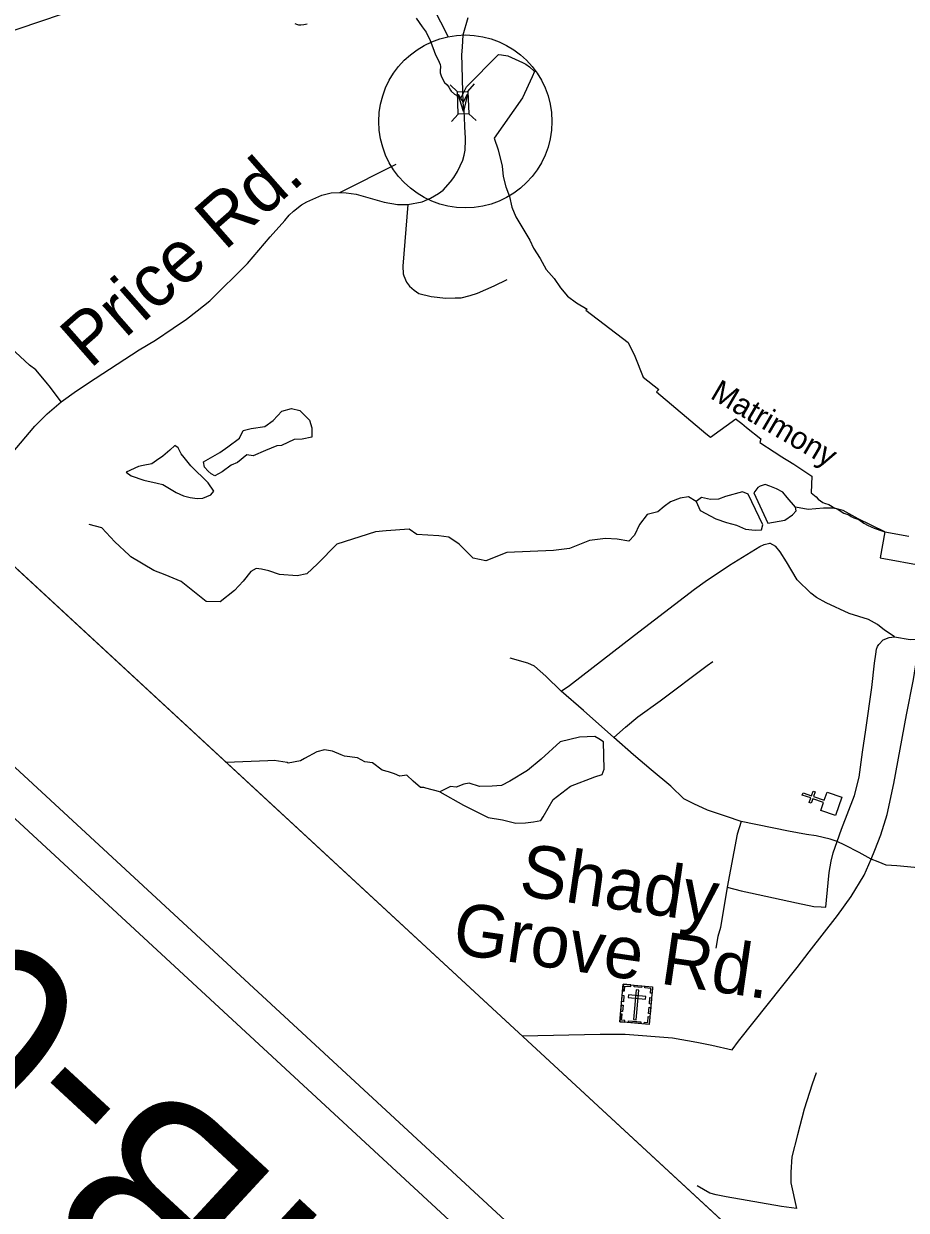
# Model space of a CAD drawing. Extents: x 1766669 to 1770980, y 998119 to 1002502.
# Drawn here: x 1767070.6 to 1767327.3, y 999494 to 999839.2 of the extents above; entities that cross this region are included whole.
import ezdxf

# ---------------------------------------------------------------- set-up
doc = ezdxf.new("R2010")
doc.units = 0
for name, color, linetype in [('Default', 7, 'Continuous'), ('Default Symbol CELL', 7, 'Continuous'), ('Exist DTM Breakline', 7, 'Continuous'), ('Exist DTM Drainline', 7, 'Continuous'), ('Exist DTM Regular Point CELL', 7, 'Continuous'), ('Exist Other Culture Dam', 7, 'Continuous'), ('Exist Property Text', 7, 'Continuous'), ('Exist Roads EOP', 7, 'Continuous'), ('Exist Roads EOP Other', 7, 'Continuous'), ('Exist Structure Minor Paved Ditch or Gutter', 7, 'Continuous'), ('Exist Structure Minor Pipes RCP 24 Inch', 7, 'Continuous'), ('Exist Survey Setup Group', 7, 'Continuous'), ('Exist Utilities Sanitary Sewer UG Line', 7, 'Continuous')]:
    doc.layers.add(name, color=color, linetype=linetype)

msp = doc.modelspace()

# ---------------------------------------------------------------- linework, layer by layer
at = {"layer": 'Default'}
msp.add_lwpolyline([(1766911.45, 999825.82), (1767342.39, 1000292.03), (1767769.56, 999897.17), (1767338.62, 999430.96)], close=True, dxfattribs=at)
at = {"layer": 'Default Symbol CELL'}
for p, q in [((1768196.36, 998579.87), (1766849, 999825.3)), ((1767395.61, 999378.28), (1766911.45, 999825.82)), ((1768487.42, 998295.86), (1766841.54, 999817.23))]:
    msp.add_line(p, q, dxfattribs=at)
msp.add_lwpolyline([(1767251.23, 999959.27), (1767173.81, 999875.14), (1767194.02, 999835.43)], dxfattribs=at)
at = {"layer": 'Exist DTM Breakline'}
msp.add_line((1767162.57, 999790.09), (1767178.91, 999798.33), dxfattribs=at)
for points in [[(1767198.42, 999816.26), (1767198.19, 999823.02), (1767198.13, 999827.11), (1767198.01, 999830.13), (1767198.18, 999832.42), (1767198.42, 999835.93), (1767199.89, 999841.01)], [(1767182.29, 999786.59), (1767186.45, 999787.39), (1767188.87, 999788.48), (1767191.25, 999789.82), (1767192.56, 999790.83), (1767194.68, 999793.2), (1767195.68, 999794.51), (1767196.72, 999796.25), (1767198.27, 999799.52), (1767198.71, 999801), (1767198.97, 999802.4), (1767199.09, 999805.38), (1767199.11, 999805.93), (1767198.93, 999809.18), (1767198.82, 999812.13), (1767198.69, 999813.48), (1767198.42, 999816.26)], [(1767135.72, 999769.45), (1767142.25, 999777.24), (1767146.52, 999781.96), (1767147.79, 999783.52), (1767149.02, 999784.66), (1767151.39, 999786.48), (1767152.91, 999787.42), (1767157.27, 999789.37), (1767160.02, 999789.97), (1767162.57, 999790.09)], [(1767162.57, 999790.09), (1767164.4, 999790.03), (1767167.31, 999789.62), (1767175.39, 999787.26), (1767179.28, 999786.58), (1767182.29, 999786.59)], [(1767182.29, 999786.59), (1767180.86, 999768.68), (1767180.99, 999766.43), (1767181.18, 999765.84), (1767181.94, 999764.03), (1767182.75, 999762.83), (1767184.15, 999761.66), (1767185.48, 999760.74), (1767189.1, 999759.81), (1767193.37, 999759.33), (1767196.1, 999759.47), (1767197.85, 999759.46), (1767200.41, 999760.14), (1767202.58, 999760.81), (1767207.45, 999762.96), (1767211.17, 999764.78)], [(1767081.5, 999729.23), (1767078.42, 999733.41), (1767077.12, 999734.95), (1767074.1, 999738.51), (1767072.32, 999739.83), (1767062.55, 999748.8), (1767058.99, 999752.71), (1767057.13, 999754.84), (1767056.29, 999756.3), (1767056.33, 999757.04), (1767056.65, 999758.12), (1767058.82, 999761.77), (1767059.06, 999762.9), (1767059.05, 999763.97), (1767058.97, 999764.77), (1767057.44, 999767.04), (1767055.19, 999770.52), (1767050.27, 999776.85), (1767048.82, 999778.68), (1767047.32, 999780.81)], [(1767081.5, 999729.23), (1767085.92, 999732.4), (1767091.36, 999735.95), (1767104.2, 999744.3), (1767108.93, 999747.18), (1767114.06, 999750.61), (1767117.9, 999753.21), (1767121.07, 999755.65), (1767124.73, 999758.54), (1767135.72, 999769.45)], [(1767052.3, 999695.62), (1767067.05, 999714.05), (1767073.82, 999722.16), (1767077.44, 999725.69), (1767081.5, 999729.23)], [(1767226.89, 999644.97), (1767229.34, 999646.69), (1767248.2, 999661.3), (1767265.7, 999674.72), (1767268.75, 999676.94), (1767275.85, 999681.71), (1767284.63, 999687.14), (1767285.9, 999687.73), (1767287.56, 999688.12)], [(1767323.81, 999660.83), (1767322.91, 999661.46), (1767320.91, 999662.73), (1767318.86, 999664.42), (1767316.25, 999665.91), (1767310.68, 999667.58), (1767303.93, 999670.73), (1767301.14, 999672.22), (1767299.46, 999673.51), (1767295.58, 999677.42), (1767292.43, 999682.6), (1767290.56, 999685.51), (1767289.35, 999687.13), (1767287.56, 999688.12)], [(1767307.12, 999601.28), (1767308.43, 999604.89), (1767312.17, 999614.61), (1767313.54, 999619.98), (1767314.56, 999627.3), (1767315.5, 999633.74), (1767317.22, 999646.05), (1767317.99, 999653.16), (1767318.4, 999655.82), (1767318.57, 999657.28), (1767318.9, 999657.99), (1767319.33, 999658.58), (1767320.58, 999659.91), (1767322.28, 999660.6), (1767323.81, 999660.83)], [(1767317.09, 999596.14), (1767318.12, 999598.72), (1767319.91, 999603.19), (1767321.74, 999609.09), (1767323.61, 999618.13), (1767327.36, 999638.16), (1767329.35, 999648.37), (1767330.48, 999655.24), (1767331.7, 999660.2)], [(1767323.81, 999660.83), (1767328.39, 999660.05), (1767331.7, 999660.2)], [(1767226.89, 999644.97), (1767222.41, 999649.4), (1767219.19, 999652.26), (1767217.22, 999653.2), (1767212.02, 999654.58)], [(1767242.21, 999631.49), (1767245.62, 999634.53), (1767249.22, 999637.51), (1767255.7, 999642.18), (1767269.35, 999652.51), (1767270.98, 999653.65)], [(1767242.21, 999631.49), (1767233.35, 999639.35), (1767226.89, 999644.97)], [(1767279.2, 999607.1), (1767274.97, 999608.52), (1767269.44, 999610.43), (1767265.52, 999612.19), (1767262.62, 999613.67), (1767258.8, 999617.33), (1767253.1, 999622.15), (1767247.98, 999626.53), (1767242.21, 999631.49)], [(1767279.2, 999607.1), (1767278.09, 999603.45), (1767275.15, 999587.99)], [(1767307.12, 999601.28), (1767305.17, 999601.97), (1767301.08, 999602.88), (1767298.23, 999603.31), (1767292.99, 999604.31), (1767279.2, 999607.1)], [(1767303.89, 999582.21), (1767304.04, 999584.25), (1767304.87, 999592.3), (1767305.44, 999595.59), (1767306.04, 999597.97), (1767307.12, 999601.28)], [(1767317.09, 999596.14), (1767313.57, 999598.03), (1767309.43, 999600.17), (1767307.12, 999601.28)], [(1767276.65, 999540.7), (1767278.44, 999543.13), (1767295.51, 999564.58), (1767298.99, 999569.2), (1767307.26, 999579.71), (1767311.28, 999585.31), (1767314.98, 999591.5), (1767317.09, 999596.14)], [(1767361.52, 999590.67), (1767324.52, 999594.21), (1767321.41, 999594.43), (1767319.05, 999595.32), (1767317.09, 999596.14)], [(1767275.15, 999587.99), (1767273.21, 999576.27), (1767272.44, 999573.63), (1767271.84, 999570.19)], [(1767275.15, 999587.99), (1767279.21, 999586.95), (1767281.98, 999586.32), (1767295.32, 999583.44), (1767300.35, 999582.35), (1767302.48, 999582.25), (1767303.89, 999582.21)], [(1767215.52, 999544.75), (1767238.25, 999545.25), (1767245.56, 999545.22), (1767259.29, 999544.1), (1767266.33, 999542.91), (1767270.67, 999542), (1767276.65, 999540.7)], [(1767301.09, 999533.99), (1767299.85, 999530.65), (1767297.58, 999523.37), (1767295.67, 999515.95), (1767293.99, 999509.53), (1767293.65, 999505.04), (1767293.74, 999502), (1767295.38, 999494.53)], [(1767295.38, 999494.53), (1767291, 999495.12), (1767274.84, 999497.88), (1767272.02, 999498.46), (1767270.15, 999498.94), (1767266.49, 999501.08)]]:
    msp.add_lwpolyline(points, dxfattribs=at)
at = {"layer": 'Exist DTM Drainline'}
for points in [[(1767244.96, 999559.73), (1767253.49, 999558.96), (1767252.5, 999548.05), (1767243.97, 999548.82)], [(1767244.8, 999557.87), (1767245.28, 999557.83), (1767245.41, 999559.21), (1767247.14, 999559.05), (1767247.19, 999559.53), (1767244.96, 999559.73)], [(1767249.52, 999558.05), (1767248.72, 999558.12), (1767247.93, 999549.44), (1767248.73, 999549.36)], [(1767248.14, 999559.44), (1767250.36, 999559.24), (1767250.31, 999558.75), (1767248.09, 999558.95)], [(1767253.33, 999557.1), (1767252.84, 999557.14), (1767252.97, 999558.52), (1767251.23, 999558.68), (1767251.27, 999559.15), (1767253.49, 999558.95)], [(1767244.51, 999554.7), (1767244.67, 999556.55), (1767245.16, 999556.51), (1767244.99, 999554.65)], [(1767246.45, 999556.66), (1767246.37, 999555.86), (1767251.42, 999555.4), (1767251.49, 999556.2)], [(1767252.55, 999554.01), (1767252.72, 999555.87), (1767253.21, 999555.82), (1767253.04, 999553.97)], [(1767245.39, 999548.7), (1767245.44, 999549.19), (1767244.49, 999549.27), (1767244.65, 999551), (1767244.17, 999551.05), (1767243.97, 999548.82)], [(1767244.24, 999551.82), (1767244.41, 999553.67), (1767244.9, 999553.63), (1767244.73, 999551.77)], [(1767252.3, 999551.19), (1767252.46, 999553.04), (1767252.95, 999553), (1767252.78, 999551.14)], [(1767246.48, 999549.09), (1767250.11, 999548.76), (1767250.07, 999548.27), (1767246.44, 999548.6)], [(1767251.08, 999548.18), (1767251.13, 999548.67), (1767252.07, 999548.58), (1767252.23, 999550.31), (1767252.7, 999550.27), (1767252.5, 999548.05)]]:
    msp.add_lwpolyline(points, close=True, dxfattribs=at)
at = {"layer": 'Exist Other Culture Dam'}
msp.add_lwpolyline([(1767191.59, 999615.7), (1767198.53, 999611.84), (1767205.7, 999608.24), (1767209.86, 999607.57), (1767213.7, 999606.57), (1767216.51, 999606.68), (1767218.9, 999607.02), (1767220.95, 999607.35), (1767221.65, 999608.45), (1767224.6, 999613.53), (1767229.57, 999617.36), (1767236.66, 999620.04), (1767238.78, 999620.79), (1767239.39, 999622.3), (1767239.24, 999630.23), (1767237.88, 999631.17), (1767236.7, 999631.79), (1767232.24, 999631.61), (1767226.58, 999630.31), (1767221.08, 999625.22), (1767217.07, 999621.92), (1767211.98, 999618.82), (1767209.55, 999617.57), (1767206.83, 999617.38), (1767203.19, 999617.24), (1767200.17, 999618.28), (1767198.62, 999617.97), (1767196.34, 999617.05), (1767194.76, 999617.24)], close=True, dxfattribs=at)
at = {"layer": 'Exist Property Text'}
for p, q in [((1767196.75, 999819.41), (1767194.57, 999821.42)), ((1767199.72, 999819.53), (1767201.73, 999821.71)), ((1767194.98, 999810.73), (1767196.99, 999812.91)), ((1767202.21, 999811.02), (1767200.03, 999813.03))]:
    msp.add_line(p, q, dxfattribs=at)
msp.add_lwpolyline([(1767196.99, 999812.91), (1767196.74, 999819.41), (1767199.77, 999819.53), (1767200.03, 999813.03)], close=True, dxfattribs=at)
at = {"layer": 'Exist Roads EOP'}
for points in [[(1767127.45, 999852.04), (1767117.35, 999852.94), (1767104.67, 999845.68), (1767096.41, 999842.6), (1767081.44, 999841.91), (1767056.77, 999833.6), (1767028.19, 999831.39), (1767010.54, 999827.31)], [(1767266.14, 999700.18), (1767263.95, 999701.54), (1767261.49, 999701.19), (1767258.71, 999700.14), (1767256.88, 999698.7), (1767254.98, 999697.17), (1767251.93, 999696.37), (1767249.65, 999693.55), (1767248.24, 999690.41), (1767246.6, 999688.64), (1767243.16, 999689.19), (1767239.81, 999689.48), (1767235.14, 999688.87), (1767229.33, 999686.51), (1767224.65, 999685.9), (1767211.13, 999685.32), (1767204.98, 999682.94), (1767201.28, 999683.74), (1767197.27, 999687.77), (1767194.2, 999689.78), (1767191.28, 999690.18), (1767184.94, 999690.62), (1767182.74, 999692.15), (1767176.01, 999691.63), (1767172.95, 999691.34), (1767161.63, 999687.82), (1767156, 999682.09), (1767152.96, 999679.15), (1767150.16, 999678.61), (1767145.02, 999678.92), (1767141.9, 999679.99), (1767139.74, 999680.51), (1767138.24, 999680.66), (1767136.65, 999679.83), (1767134.37, 999677.01), (1767131.91, 999674.34), (1767127.68, 999671.02), (1767123.66, 999671.11), (1767119.78, 999674.21), (1767116.34, 999676.89), (1767111.73, 999678.85), (1767108.43, 999680.09), (1767101.78, 999684.1), (1767101.25, 999684.59), (1767097.08, 999688.45), (1767093.33, 999692.57), (1767089.66, 999693.52)], [(1767321.07, 999691.42), (1767313.3, 999695.15), (1767308.94, 999697.54), (1767306.26, 999698.21), (1767303.18, 999698.26), (1767298.75, 999697.91), (1767295.09, 999698.58)], [(1767321.07, 999691.42), (1767327.97, 999690.11)], [(1767191.59, 999615.7), (1767187.58, 999616.79), (1767186.99, 999617.01), (1767186, 999616.97), (1767183.86, 999618.79), (1767181.97, 999620.54), (1767180, 999620.29), (1767178.4, 999620.98), (1767176.72, 999621.57), (1767174.88, 999622), (1767172.07, 999624.12), (1767169.83, 999624.44), (1767167.71, 999625.6), (1767163.89, 999626.11), (1767162.96, 999626.49), (1767160.44, 999627.55), (1767158.11, 999627.95), (1767155.82, 999627.37), (1767152.25, 999625.41), (1767151.12, 999624.7), (1767147.51, 999624.06), (1767147.25, 999624.3), (1767143.43, 999624.81), (1767141.61, 999624.74), (1767129.5, 999624.26)]]:
    msp.add_lwpolyline(points, dxfattribs=at)
at = {"layer": 'Exist Roads EOP Other'}
msp.add_lwpolyline([(1767199.7, 999818.74), (1767198.49, 999813.64), (1767196.99, 999818.66), (1767198.42, 999816.26)], close=True, dxfattribs=at)
at = {"layer": 'Exist Structure Minor Paved Ditch or Gutter'}
msp.add_lwpolyline([(1767302.4, 999610.33), (1767303.2, 999612.65), (1767300.11, 999613.72), (1767299.65, 999612.42), (1767299, 999612.65), (1767299.46, 999613.95), (1767297.01, 999614.8), (1767297.24, 999615.45), (1767299.68, 999614.6), (1767300.14, 999615.9), (1767300.78, 999615.68), (1767300.33, 999614.38), (1767303.43, 999613.3), (1767304.24, 999615.64), (1767308.57, 999614.14), (1767306.72, 999608.83)], close=True, dxfattribs=at)
at = {"layer": 'Exist Structure Minor Pipes RCP 24 Inch'}
for points in [[(1767184.73, 999840.8), (1767186.45, 999838.27), (1767187.6, 999836.72), (1767188.83, 999834.28), (1767189.61, 999832.32), (1767190.34, 999830.18), (1767191.06, 999828.87), (1767191.41, 999828.07), (1767191.67, 999827.3), (1767191.77, 999826.72), (1767191.67, 999825.48), (1767191.74, 999824.95), (1767192.1, 999823.78), (1767193, 999822.15), (1767193.74, 999821.4), (1767194.22, 999820.77), (1767194.71, 999819.91), (1767194.95, 999819.63), (1767195.88, 999818.71), (1767197.77, 999817.73), (1767199.33, 999820.84), (1767208.71, 999830.24), (1767209.51, 999830.18), (1767211.36, 999829.82), (1767215.62, 999827.88), (1767216.64, 999827.49), (1767217.68, 999826.68), (1767219.18, 999825.28), (1767218.45, 999823.74), (1767215.69, 999817.67), (1767207.44, 999805.95), (1767208.61, 999802.5), (1767209.7, 999797.73), (1767210.07, 999794.72), (1767210.84, 999791.74), (1767211.87, 999788.98), (1767212.55, 999785.79), (1767213.75, 999783.05), (1767217.78, 999776.26), (1767218.88, 999773.94), (1767220.8, 999770.94), (1767222.52, 999767.74), (1767224.86, 999765.12), (1767226.7, 999762.37), (1767228.7, 999759.93), (1767231.36, 999757.96), (1767234.44, 999756.14), (1767234.12, 999755.82), (1767246.38, 999746.46), (1767248.33, 999742.5), (1767250.74, 999736.33), (1767255.26, 999732.8), (1767254.65, 999732.11), (1767268.94, 999719.94), (1767270.3, 999718.87), (1767277.66, 999724.28), (1767277.91, 999724.07), (1767279.42, 999722.87), (1767280.83, 999721.74), (1767284.95, 999718.46), (1767284.64, 999717.36), (1767288.83, 999714.68), (1767290.21, 999713.8), (1767290.63, 999713.53), (1767294.53, 999711.03), (1767299.76, 999707.61), (1767299.65, 999702.7), (1767301.04, 999701.55), (1767301.63, 999700.89), (1767303.02, 999699.9), (1767303.5, 999699.67), (1767304.74, 999699.32), (1767306.53, 999698.26), (1767307.12, 999698.07), (1767308.32, 999697.29), (1767309.14, 999696.79), (1767310.57, 999696.29), (1767311.21, 999695.86), (1767311.97, 999695.45), (1767313.47, 999694.96), (1767314.89, 999693.89), (1767316.2, 999693.21), (1767317.92, 999692.48), (1767320.12, 999691.65), (1767321.07, 999691.42), (1767319.64, 999683.79), (1767332.39, 999681.46)], [(1767149.4, 999839.29), (1767149.93, 999839.04), (1767150.52, 999838.92), (1767151.18, 999838.92), (1767152.07, 999839.01), (1767153.05, 999839.21)]]:
    msp.add_lwpolyline(points, dxfattribs=at)
at = {"layer": 'Exist Survey Setup Group'}
msp.add_circle((1767199.05, 999810.77), 25.17, dxfattribs=at)
at = {"layer": 'Exist Utilities Sanitary Sewer UG Line'}
for points in [[(1767122.89, 999711.77), (1767127.66, 999714.43), (1767129.99, 999716.06), (1767133.31, 999718.67), (1767134.46, 999720.81), (1767136.74, 999721.41), (1767140.69, 999722.04), (1767143.19, 999723.76), (1767145.69, 999726.47), (1767148.48, 999727.26), (1767150.86, 999726.63), (1767153.7, 999723.83), (1767154.38, 999721.64), (1767154.36, 999718.94), (1767151.61, 999718.37), (1767149.26, 999718.23), (1767145.57, 999716.46), (1767144.16, 999716.36), (1767140.92, 999715.08), (1767137.36, 999713.45), (1767135.46, 999713.8), (1767132.77, 999711.51), (1767130.88, 999710.8), (1767128.35, 999708.86), (1767126.17, 999707.67), (1767125.08, 999708.26), (1767124.24, 999709.04), (1767123.21, 999710.16)], [(1767100.38, 999708.77), (1767101.8, 999707.63), (1767105.56, 999706.36), (1767109.36, 999705.57), (1767111.04, 999705.17), (1767114.98, 999702.84), (1767117.02, 999701.86), (1767119.05, 999701.38), (1767121.07, 999701.08), (1767122.69, 999701.14), (1767125.04, 999702.17), (1767125.86, 999703.23), (1767124.22, 999705.64), (1767119.2, 999710.53), (1767117.22, 999713.02), (1767116.37, 999714.05), (1767115.49, 999715.77), (1767114.57, 999716.46), (1767113.08, 999715.12), (1767111.01, 999713.41), (1767109.18, 999712.15), (1767107.81, 999711.11), (1767105.35, 999710.67), (1767103.95, 999710.4)], [(1767266.14, 999700.18), (1767267.36, 999697.57), (1767271.89, 999695.19), (1767275.01, 999694.12), (1767277.87, 999693.29), (1767280.47, 999692.19), (1767283.31, 999691.88), (1767285.18, 999691.95), (1767285.55, 999693.42), (1767281.27, 999702.31), (1767279.62, 999703.01), (1767274.72, 999701.62), (1767272.7, 999700.86), (1767270.31, 999700.77), (1767267.72, 999701.35)], [(1767282.97, 999702.72), (1767286.99, 999693.9), (1767291.91, 999694.78), (1767294.16, 999696.32), (1767295.22, 999697.47), (1767295.09, 999698.58), (1767292.59, 999701.39), (1767291.33, 999702.88), (1767289.5, 999703.92), (1767287.59, 999704.69), (1767286.2, 999705.15), (1767284.77, 999704.67), (1767284.1, 999704.3)]]:
    msp.add_lwpolyline(points, close=True, dxfattribs=at)

# ---------------------------------------------------------------- texts
at = {"layer": 'Default Symbol CELL'}
for s, height, rotation, p in [('Price Rd.', 15.235, 41.2932, (1767089.89, 999738.57)), ('TIP PROJECT: HB-0035', 54.9341, 137.2512, (1767566.03, 999113.48)), ('Shady', 15.235, 351.7213, (1767214.28, 999585.7)), ('Grove Rd.', 15.235, 351.7213, (1767194.85, 999568.76))]:
    msp.add_text(s, height=height, rotation=rotation, dxfattribs=at).set_placement(p)
at = {"layer": 'Exist DTM Regular Point CELL'}
msp.add_text('Matrimony', height=6.452, rotation=329.6063, dxfattribs=at).set_placement((1767269.95, 999730.39))

doc.saveas('drawing.dxf')
